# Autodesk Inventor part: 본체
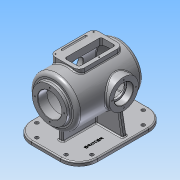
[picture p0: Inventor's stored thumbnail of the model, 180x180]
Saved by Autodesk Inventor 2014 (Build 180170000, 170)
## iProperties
Created: 2016-02
Part Number: 본체
Material: 알루미늄 6061
Document SubType Name: Modeling
Designer: mduedu
Density: 2.71 g/cm^3
Appearance: 알루미늄 - 평지
Mass: 4129.67 g
Surface Area: 2907.51 cm^2
Volume: 1523.86 cm^3
Author: mduedu
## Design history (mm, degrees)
sketch "스케치2"
  geometry: L1 (0, 100)-(0, -100); L2 (65, -75.993)-(65, 100); L3 (65, 100)-(0, 100); A1 r 100 centre (0, 0) between (0, -100) and (65, -75.993); 2 further points
  constraints: 6 end point, 2 midpoint, 2 point on circle, 1 centre point, 1 coincident, 1 horizontal, 1 parallel, 1 vertical
  dimensions: "d3" = 200 distance of L1.start L1.end; "d5" = 130 diameter of L2 L1; "d6" = 100 radius of A1
revolve "회전1" sketch "스케치2" stored, may be unused: angle "d7" = 90 deg
sketch "스케치3"
  geometry: C1 r 47.5 at (0, 0); 1 further point
  constraints: 1 centre point, 1 coincident
  dimensions: "d8" = 95 diameter of C1
extrude "돌출2" join sketch "스케치3" distance "d10" = 10; taper "d11" = 0 deg
sketch "스케치5"
  geometry: L1 (47.5, 110)-(47.5, 100) reference; L2 (47.5, 100)-(65, 100) reference; L3 (65, 100)-(65, -75.993) reference; L4 (-65, -75.993)-(-65, 100) reference; L5 (-65, 100)-(-47.5, 100) reference; L6 (-47.5, 100)-(-47.5, 110) reference; L7 (-47.5, 110)-(47.5, 110) reference; L8 (55, 85)-(55, -71.239); L9 (0, 85)-(55, 85); L10 (0, 85)-(0, -90); A1 r 100 centre (0, 0) between (0, -100) and (65, -75.993) reference; A2 r 100 centre (0, 0) between (-65, -75.993) and (0, -100) reference; A3 r 90 centre (0, 0) between (0, -90) and (55, -71.239); 1 further point
  constraints: 6 end point, 2 point on circle, 1 centre point, 1 parallel, 1 perpendicular, 1 point on line, 1 vertical
  dimensions: "d13" = 10 distance between parallel lines of L3 L8; "d14" = 10 radial gap between concentric circles of A3 A1; "d15" = 15 distance between parallel lines of L9 L2
revolve "회전2" sketch "스케치5" stored, may be unused: angle "d16" = 90 deg
hole "구멍1" diameter "d19" = 65; stored, may be unused: countersink angle "d23" = 90 deg, drill point angle "d25" = 118 deg; dims "d17" = 10, "d18" = 10, "d20" = 6, "d21" = 4, "d22" = 2, "d24" = 8
node "작업 평면1"
sketch "스케치6"
  geometry: L1 (47.5, 110)-(-47.5, 110) reference; C1 r 40 at (0, -17); 1 further point
  constraints: 1 centre point, 1 vertical alignment
  dimensions: "d27" = 80 diameter of C1; "d29" = 127 distance from line of C1.centre L1
extrude "돌출3" join sketch "스케치6" stored distance "d30" = 10; taper "d31" = 0 deg
hole "구멍2" diameter "d34" = 42; stored, may be unused: countersink angle "d38" = 90 deg, drill point angle "d40" = 118 deg; dims "d32" = 10, "d33" = 10, "d35" = 6, "d36" = 52, "d37" = 18, "d39" = 8
sketch "스케치7" dims "d41" = 65
  geometry: C1 r 40 at (0, 0) reference; 3 further points
  constraints: 2 vertical alignment, 1 coincident, 2 other
hole "구멍3" sketch "스케치7" at (0, 32.5) diameter "d43" = 3.242; stored, may be unused: countersink angle "d47" = 90 deg, drill point angle "d49" = 118 deg; dims "d44" = 11, "d45" = 13, "d46" = 18, "d48" = 13
sketch "스케치8" dims "d53" = 80
  geometry: 3 further points
  constraints: 2 vertical alignment, 1 coincident, 2 other
hole "구멍4" sketch "스케치8" at (0, 40) diameter "d56" = 3.242; stored, may be unused: countersink angle "d60" = 90 deg, drill point angle "d62" = 118 deg; dims "d57" = 11, "d58" = 13, "d59" = 18, "d61" = 13
fillet "모깎기1" dims "d66" = 10
fillet "모깎기2" dims "d67" = 3
fillet "모깎기3" dims "d68" = 0.3
chamfer "모따기1" distance "d69" = 1; stored, may be unused: second distance "d70" = 2, angle "d71" = 45 deg
node "작업 평면5"
sketch "스케치23"
  geometry: L1 (6, 80)-(-6, 80); L2 (-6, 80)-(-6, -60); L3 (-6, -60)-(6, -60); L4 (6, -60)-(6, 80); L5 (-55, 100)-(55, 100) reference; 2 further points
  constraints: 8 end point, 2 parallel, 1 horizontal, 1 midpoint, 1 perpendicular, 1 vertical alignment
  dimensions: "d177" = 12 distance of L1.start L1.end; "d179" = 140 distance of L3.end L1.start; "d180" = 20 distance between parallel lines of L1 L5
extrude "돌출14" join sketch "스케치23" stored distance "d181" = 10; taper "d182" = 0 deg
node "작업 평면6"
sketch "스케치15"
  geometry: L1 (-30, 60)-(50, 60); L2 (50, 60)-(50, -60); L3 (50, -60)-(-30, -60); L4 (-30, -60)-(-30, 60); 3 further points
  constraints: 8 end point, 2 parallel, 1 horizontal, 1 horizontal alignment, 1 midpoint, 1 perpendicular, 1 vertical alignment
  dimensions: "d110" = 80 distance of L2.end L3.end; "d112" = 60 distance from line of L3 point (10, 0); "d113" = 120 distance of L1.end L2.end; "d149" = 30 distance from line of L4 point (0, 0)
extrude "돌출8" join sketch "스케치15" stored distance "d114" = 10; taper "d115" = 0 deg
fillet "모깎기7" dims "d116" = 15
sketch "스케치16"
  geometry: L1 (-30, -45)-(-30, 45) reference; L2 (-15, 60)-(35, 60) reference; L3 (35, -60)-(-15, -60) reference; L4 (-20, -45)-(-20, 45); L5 (-15, 50)-(15, 50); L6 (20, 45)-(20, -45); L7 (15, -50)-(-15, -50); L8 (50, 45)-(50, -45) reference; A1 r 15 centre (-15, -45) between (-30, -45) and (-15, -60) reference; A2 r 15 centre (-15, 45) between (-15, 60) and (-30, 45) reference; A3 r 5 centre (-15, -45) between (-20, -45) and (-15, -50); A4 r 5 centre (-15, 45) between (-15, 50) and (-20, 45); A5 r 5 centre (15, 45) between (20, 45) and (15, 50); A6 r 5 centre (15, -45) between (15, -50) and (20, -45); A7 r 15 centre (35, 45) between (50, 45) and (35, 60) reference; A8 r 15 centre (35, -45) between (35, -60) and (50, -45) reference
  constraints: 8 end point, 8 point on circle, 4 centre point, 2 equal radius, 3 other
  dimensions: "d137" = 10 distance between parallel lines of L4 L1; "d150" = 40 distance between parallel lines of L6 L4; "d151" = 100 distance between parallel lines of L7 L5
extrude "돌출9" cut sketch "스케치16" stored distance "d118" = 10; taper "d119" = 0 deg
fillet "모깎기8" dims "d120" = 3
sketch "스케치17"
  geometry: L1 (-30, -45)-(-30, 45) reference; L2 (-20, 45)-(-20, -45) reference; L3 (-15, -50)-(15, -50) reference; L4 (20, -45)-(20, 45) reference; L5 (15, 50)-(-15, 50) reference; L6 (-15, 60)-(35, 60) reference; L7 (35, -60)-(-15, -60) reference; L8 (15, 55)-(-15, 55); L9 (-25, 45)-(-25, -45); L10 (-15, -55)-(15, -55); L11 (25, -45)-(25, 45); L12 (50, 45)-(50, -45) reference; L13 (35, 55)-(-15, 55); L14 (-25, 45)-(-25, -45); L15 (-15, -55)-(35, -55); L16 (45, -45)-(45, 45); A1 r 5 centre (-15, 45) between (-15, 50) and (-20, 45) reference; A2 r 5 centre (-15, -45) between (-20, -45) and (-15, -50) reference; A3 r 5 centre (15, -45) between (15, -50) and (20, -45) reference; A4 r 5 centre (15, 45) between (20, 45) and (15, 50) reference; A5 r 15 centre (-15, 45) between (-15, 60) and (-30, 45) reference; A6 r 15 centre (-15, -45) between (-30, -45) and (-15, -60) reference; A7 r 10 centre (-15, 45) between (-15, 55) and (-25, 45); A8 r 10 centre (-15, -45) between (-25, -45) and (-15, -55); A9 r 10 centre (15, -45) between (15, -55) and (25, -45); A10 r 10 centre (15, 45) between (25, 45) and (15, 55); A11 r 15 centre (35, 45) between (50, 45) and (35, 60) reference; A12 r 15 centre (35, -45) between (35, -60) and (50, -45) reference; A13 r 10 centre (-15, 45) between (-15, 55) and (-25, 45); A14 r 10 centre (-15, -45) between (-25, -45) and (-15, -55); A15 r 10 centre (35, -45) between (35, -55) and (45, -45); A16 r 10 centre (35, 45) between (45, 45) and (35, 55); 6 further points
  constraints: 18 point on circle, 16 end point, 8 centre point, 4 midpoint, 4 tangent, 11 other
  dimensions: "d138" = 5 distance between parallel lines of L8 L6; "d157" = 5 distance between parallel lines of L12 L16
hole "구멍5" sketch "스케치17" at (-25, 0), (42.071, 52.071), (42.071, -52.071) diameter "d122" = 3.242; stored, may be unused: countersink angle "d126" = 90 deg, drill point angle "d128" = 118 deg; dims "d123" = 9, "d124" = 13, "d125" = 18, "d127" = 11
sketch "스케치19"
  geometry: L1 (-50, 70)-(-35, 70) reference; L2 (-50, 42.603)-(-50, 70) reference; C1 r 2.5 at (-43, 70); 1 further point
  constraints: 1 centre point, 1 point on line
  dimensions: "d152" = 5 diameter of C1; "d153" = 7 distance from line of C1.centre L2
extrude "돌출11" cut sketch "스케치19" stored distance "d154" = 70; taper "d155" = 0 deg
fillet "모깎기11" dims "d156" = 2.5
sketch "스케치20"
  geometry: L1 (-90, 120)-(90, 120); L2 (90, 120)-(90, -120); L3 (90, -120)-(-90, -120); L4 (-90, -120)-(-90, 120); 3 further points
  constraints: 8 end point, 2 parallel, 2 vertical alignment, 1 coincident, 1 horizontal, 1 midpoint, 1 perpendicular
  dimensions: "d162" = 180 distance of L1.start L1.end; "d164" = 240 distance of L1.end L2.end; "d165" = 120 distance from line of L1 point (0, 0)
extrude "돌출12" join sketch "스케치20" distance "d166" = 10; taper "d167" = 0 deg
fillet "모깎기12" dims "d168" = 50
node "작업 평면8"
  node "작업축1"
sketch "스케치24"
  geometry: L1 (128, 34.121)-(127.026, 32.5) reference; L2 (127.026, 32.5)-(128, 30.879) reference; L3 (128, 30.879)-(141, 30.879) reference; L4 (141, 30.879)-(141, 27) reference; L5 (141, 27)-(140, 26) reference; L6 (140, 26)-(123.3, 26) reference; L7 (123, 25.7)-(123, 21) reference; L8 (123, 21)-(116.833, 21) reference; L9 (86, 51.235)-(86, 70) reference; L10 (86, 70)-(106.5, 70) reference; L11 (111.5, 70)-(116, 70) reference; L12 (116, 70)-(116, 42.603) reference; L13 (118.678, 40)-(141, 40) reference; L14 (141, 40)-(141, 34.121) reference; L15 (141, 34.121)-(128, 34.121) reference; L16 (4, -34.121)-(4.974, -32.5) reference; L17 (4.974, -32.5)-(4, -30.879) reference; L18 (4, -30.879)-(-9, -30.879) reference; L19 (-9, -30.879)-(-9, -27) reference; L20 (-9, -27)-(-8, -26) reference; L21 (-8, -26)-(8.7, -26) reference; L22 (9, -25.7)-(9, -21) reference; L23 (9, -21)-(15.167, -21) reference; L24 (116.833, -21)-(123, -21) reference; L25 (123, -21)-(123, -25.7) reference; L26 (123.3, -26)-(140, -26) reference; L27 (140, -26)-(141, -27) reference; L28 (141, -27)-(141, -30.879) reference; L29 (141, -30.879)-(128, -30.879) reference; L30 (128, -30.879)-(127.026, -32.5) reference; L31 (127.026, -32.5)-(128, -34.121) reference; L32 (128, -34.121)-(141, -34.121) reference; L33 (141, -34.121)-(141, -40) reference; L34 (141, -40)-(118.678, -40) reference; L35 (72, -64.722)-(72, -100) reference; L36 (72, -100)-(156, -100) reference; L37 (156, -100)-(156, -110) reference; L38 (156, -110)-(-24, -110) reference; L39 (-24, -110)-(-24, -100) reference; L40 (-24, -100)-(60, -100) reference; L41 (60, -100)-(60, -64.722) reference; L42 (13.322, -40)-(-9, -40) reference; L43 (-9, -40)-(-9, -34.121) reference; L44 (-9, -34.121)-(4, -34.121) reference; L45 (4.974, 32.5)-(4, 34.121) reference; L46 (4, 34.121)-(-9, 34.121) reference; L47 (-9, 34.121)-(-9, 40) reference; L48 (-9, 40)-(13.322, 40) reference; L49 (36, 59.456)-(36, 70) reference; L50 (36, 70)-(46, 70) reference; L51 (46, 70)-(46, 51.235) reference; L52 (15.167, 21)-(9, 21) reference; L53 (9, 21)-(9, 25.7) reference; L54 (8.7, 26)-(-8, 26) reference; L55 (-8, 26)-(-9, 27) reference; L56 (-9, 27)-(-9, 30.879) reference; L57 (-9, 30.879)-(4, 30.879) reference; L58 (4, 30.879)-(4.974, 32.5) reference; L59 (-1, -40)-(-11.58, -100); A1 r 0.3 centre (123.3, 25.7) between (123.3, 26) and (123, 25.7) reference; A2 r 55 centre (66, 0) between (116.833, 21) and (86, 51.235) reference; A3 r 2.5 centre (109, 70) between (106.5, 70) and (111.5, 70) reference; A4 r 3 centre (119, 42.603) between (116, 42.603) and (116.516, 40.92) reference; A5 r 0.3 centre (8.7, -25.7) between (8.7, -26) and (9, -25.7) reference; A6 r 55 centre (66, 0) between (15.167, -21) and (116.833, -21) reference; A7 r 0.3 centre (123.3, -25.7) between (123, -25.7) and (123.3, -26) reference; A8 r 65 centre (66, 0) between (72, -64.722) and (116.354, -41.103) reference; A9 r 65 centre (66, 0) between (15.646, -41.103) and (60, -64.722) reference; A10 r 65 centre (66, 0) between (34.456, 56.833) and (15.646, 41.103) reference; A11 r 3 centre (33, 59.456) between (34.456, 56.833) and (36, 59.456) reference; A12 r 55 centre (66, 0) between (46, 51.235) and (15.167, 21) reference; A13 r 0.3 centre (8.7, 25.7) between (9, 25.7) and (8.7, 26) reference; 1 further point
  constraints: 2 end point, 2 point on line, 4 other
  dimensions: "d184" = 8 distance of L59.start L42.end; "d185" = 100 deg angle of L59 L40
feature "리브2" sketch "스케치24" dims "d186" = 1, "d187" = 12, "d188" = 0, "d189" = 0, "d190" = 1, "d191" = 1
fillet "모깎기15" dims "d192" = 3
fillet "모깎기16" dims "d193" = 3
sketch "스케치25"
  geometry: L1 (90, -70)-(90, 70) reference; L2 (40, 120)-(-40, 120) reference; L3 (-90, 70)-(-90, -70) reference; L4 (-40, -120)-(40, -120) reference; L5 (-74.004, 8)-(-9, 8) reference; L6 (-80.097, 20)-(-80.097, 14) reference; L7 (-9, 26)-(-74.004, 26) reference; L8 (-9, 57)-(-9, 26) reference; L9 (3, 63)-(-3, 63) reference; L10 (9, 26)-(9, 57) reference; L11 (74.004, 26)-(9, 26) reference; L12 (80.097, 14)-(80.097, 20) reference; L13 (9, 8)-(74.004, 8) reference; L14 (9, -77)-(9, 8) reference; L15 (-3, -83)-(3, -83) reference; L16 (-9, 8)-(-9, -77) reference; L17 (-40, 105)-(40, 105); L18 (75, 70)-(75, -70); L19 (40, -105)-(-40, -105); L20 (-75, -70)-(-75, 70); C1 r 5 at (-75, 70); C2 r 5 at (-40, 105); C3 r 5 at (40, 105); C4 r 5 at (75, 70); C5 r 5 at (75, -70); C6 r 5 at (40, -105); C7 r 5 at (-40, -105); C8 r 5 at (-75, -70); A1 r 50 centre (40, 70) between (90, 70) and (40, 120) reference; A2 r 50 centre (-40, 70) between (-40, 120) and (-90, 70) reference; A3 r 50 centre (-40, -70) between (-90, -70) and (-40, -120) reference; A4 r 50 centre (40, -70) between (40, -120) and (90, -70) reference; A5 r 6 centre (-3, 57) between (-3, 63) and (-9, 57) reference; A6 r 6 centre (3, 57) between (9, 57) and (3, 63) reference; A7 r 6 centre (3, -77) between (3, -83) and (9, -77) reference; A8 r 6 centre (-3, -77) between (-9, -77) and (-3, -83) reference; A9 r 35 centre (40, 70) between (75, 70) and (40, 105); A10 r 35 centre (40, -70) between (40, -105) and (75, -70); A11 r 35 centre (-40, -70) between (-75, -70) and (-40, -105); A12 r 35 centre (-40, 70) between (-40, 105) and (-75, 70); 5 further points; 4 other entities
  constraints: 12 centre point, 8 coincident, 8 end point, 8 point on circle, 7 equal radius, 11 other
  dimensions: "d194" = 15 distance between parallel lines of L17 L2; "d195" = 10 diameter of C1
extrude "돌출15" cut sketch "스케치25" stored distance "d197" = 10; taper "d198" = 0 deg
fillet "모깎기14" dims "d170" = 3
sketch "스케치22"
  geometry: L1 (90, -70)-(90, 70) reference; 2 further points
  constraints: 1 other
  dimensions: "d174" = 40 distance from line of L1 point (50, -40); "d199" = 40 vertical distance of point (50, -40) point (0, 0)
feature "엠보싱2" sketch "스케치22" dims "d13" = 10, "d175" = 0.5, "d176" = 0
node "솔리드2"
pattern_circular "원형 패턴1" dims angle "d51" = 360 deg
mirror "대칭1"
pattern_circular "원형 패턴2" dims angle "d64" = 360 deg
mirror "대칭3"
node "투영된 루프2"
node "절단 모서리 투영1"
node "절단 모서리 투영2"
node "절단 모서리 투영3"
node "절단 모서리 투영4"
other parameters: "d26" = 75, "d183" = 0
